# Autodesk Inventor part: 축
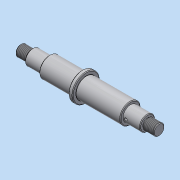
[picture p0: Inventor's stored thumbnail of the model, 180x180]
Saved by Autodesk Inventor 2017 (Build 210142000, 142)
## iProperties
Created: 2021-06
Part Number: 축
Material: 강철, 연강
Document SubType Name: Modeling
Designer: mdu
Density: 1 g/cm^3
Appearance: 흰색
CustomPartVersion: 1
Author: mdu
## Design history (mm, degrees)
sketch "주 스케치"
  geometry: L1 (0, 0)-(203, 0) reference; L2 (0, 0)-(0, 8); L3 (0, 8)-(17, 8); L4 (17, 8)-(17, 11); L5 (17, 11)-(42, 11); L6 (42, 11)-(42, 15); L7 (42, 15)-(90, 15); L8 (90, 15)-(90, 20); L9 (96, 20)-(96, 15); L10 (90, 20)-(96, 20); L11 (161, 15)-(161, 11); L12 (96, 15)-(161, 15); L13 (186, 11)-(186, 8); L14 (161, 11)-(186, 11); L15 (203, 8)-(203, 0); L16 (186, 8)-(203, 8)
  constraints: 32 end point, 9 horizontal, 8 vertical
  dimensions: "d3" = 16 diameter of L3 L1 (derived); "d4" = 22 diameter of L5 L1 (derived); "d5" = 30 diameter of L7 L1 (derived); "d6" = 40 diameter of L10 L1 (derived); "d7" = 30 diameter of L12 L1 (derived); "d8" = 22 diameter of L14 L1 (derived); "d9" = 16 diameter of L16 L1 (derived)
revolve "회전1" sketch "주 스케치" stored, may be unused: angle "d10" = 0 deg
chamfer "모따기1" distance "d11" = 1; stored, may be unused: second distance "d12" = 1, angle "d13" = 45 deg
chamfer "모따기2" distance "d14" = 1; stored, may be unused: second distance "d15" = 1, angle "d16" = 45 deg
node "키홈1"
chamfer "모따기3" distance "d17" = 1; stored, may be unused: second distance "d18" = 1, angle "d19" = 45 deg
fillet "모깎기1" dims "d20" = 0.3
chamfer "모따기4" distance "d21" = 1; stored, may be unused: second distance "d22" = 1, angle "d23" = 45 deg
chamfer "모따기5" distance "d24" = 1; stored, may be unused: second distance "d25" = 1, angle "d26" = 45 deg
fillet "모깎기2" dims "d27" = 0.3
chamfer "모따기6" distance "d28" = 1; stored, may be unused: second distance "d29" = 1, angle "d30" = 45 deg
chamfer "모따기7" distance "d31" = 1; stored, may be unused: second distance "d32" = 1, angle "d33" = 45 deg
node "키홈2"
chamfer "모따기8" distance "d34" = 1; stored, may be unused: second distance "d35" = 1, angle "d36" = 45 deg
sketch "스케치3"
  geometry: L1 (1, 8)-(17, 8) reference; L2 (17, -10)-(17, 10) reference; L3 (186, 10)-(186, -10) reference; L4 (186, 8)-(202, 8) reference; L5 (203, 7)-(203, -7) reference; L6 (0, 0)-(203, 0); L7 (17, 8)-(15.5, 8); L8 (15.5, 8)-(15.5, 7); L9 (15.5, 7)-(17, 7); L10 (17, 7)-(17, 8); L11 (186, 8)-(187.5, 8); L12 (187.5, 8)-(187.5, 7); L13 (187.5, 7)-(186, 7); L14 (186, 7)-(186, 8)
  constraints: 18 end point, 4 parallel, 2 horizontal, 2 perpendicular, 1 midpoint
  dimensions: "d37" = 14 diameter of L13 L6; "d39" = 1.5 distance of L12.end L13.end; "d40" = 14 diameter of L9 L6; "d41" = 1.5 distance of L8.end L9.end
revolve "회전2" sketch "스케치3" stored, may be unused: angle "d42" = 90 deg
feature "스레드1" dims "d43" = 10, "d44" = 0
feature "스레드2" dims "d45" = 10, "d46" = 0
sketch "스케치4"
  geometry: L1 (186, 7)-(186, -7) reference; L2 (186, 10)-(186, -10) reference; L3 (161, -11)-(185, -11) reference; L4 (165, -11)-(165, -9); L5 (165, -9)-(167, -11); L6 (165, -11)-(167, -11); 1 further point
  constraints: 6 end point, 2 point on line, 1 collinear, 1 perpendicular
  dimensions: "d47" = 21 distance from line of L2 L4.start; "d48" = 4 diameter of L5.end L4; "d49" = 45 deg angle of L4 L5
revolve "회전3" sketch "스케치4" stored, may be unused: angle "d50" = 90 deg
node "솔리드1"
feature "iFeature3:1"
feature "iFeature3:2"
node "투영된 루프1"
other parameters: "d0" = 0, "d1" = 0, "d2" = 0
